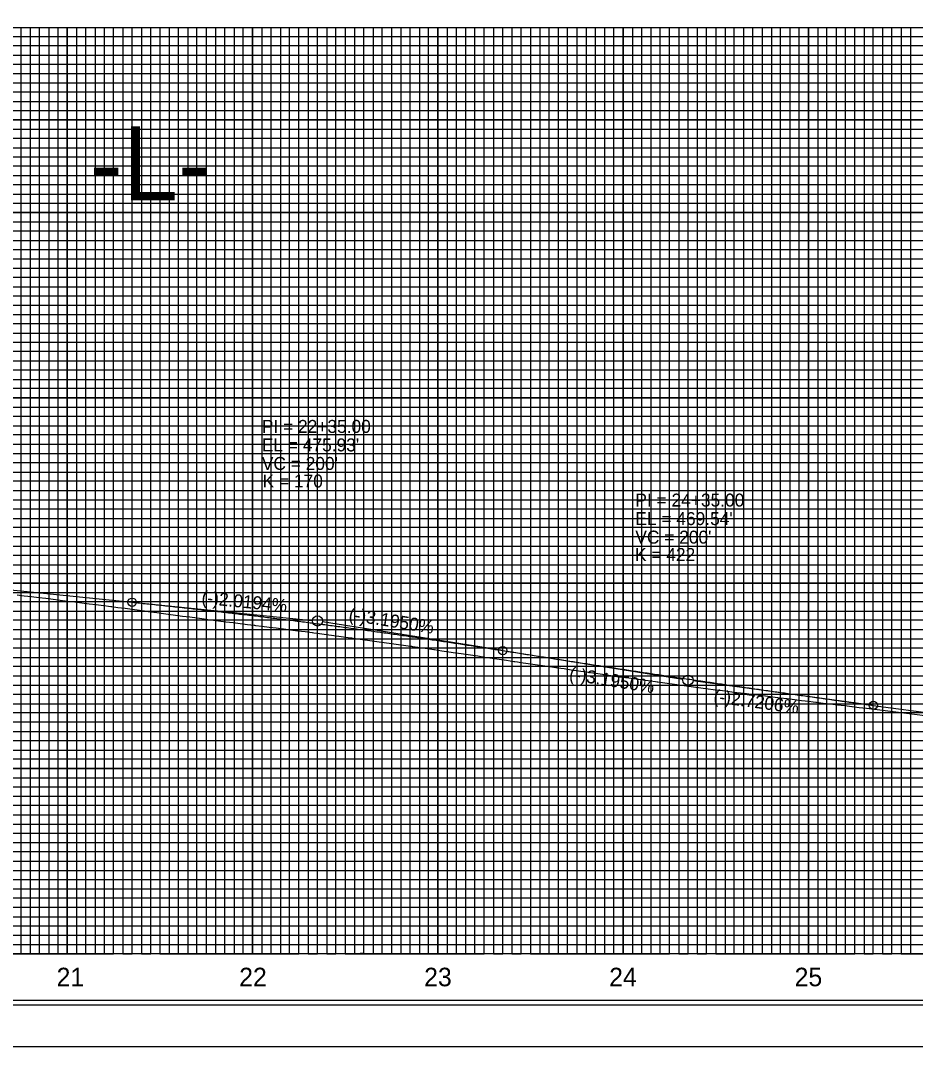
# Model space of a CAD drawing. Extents: x 571503 to 593215, y -77195 to -51828.
# Drawn here: x 583172 to 583655, y -72483 to -71929 of the extents above; entities that cross this region are included whole.
import ezdxf

# ---------------------------------------------------------------- set-up
doc = ezdxf.new("R2010")
doc.units = 0
for name, color, linetype in [('Exist Vertical Profile Ground Line', 7, 'Continuous'), ('Exist Vertical Profile Horizontal Axis Label Major', 7, 'Continuous'), ('Exist Vertical Profile Vertical Axis Label', 7, 'Continuous'), ('Prop Vertical Profile Curve Label', 7, 'Continuous'), ('Prop Vertical Profile Grade', 7, 'Continuous'), ('Prop Vertical Profile Grade Label', 7, 'Continuous'), ('Prop VPI Label', 7, 'Continuous'), ('Sheet Cutting Line CELL', 7, 'Continuous'), ('Sheet DOT Grid CELL', 7, 'Continuous'), ('Sheet Layout Profile Border Port 2', 7, 'Continuous'), ('Sheet Plot Border Inside CELL', 7, 'Continuous'), ('Sheet Plot Border Outside CELL', 7, 'Continuous'), ('Sheet Profile CELL', 7, 'Continuous'), ('Sheet Profile Grid Major CELL', 7, 'Continuous'), ('Sheet Profile Grid Middle CELL', 7, 'Continuous'), ('Sheet Profile Grid Minor CELL', 7, 'Continuous')]:
    doc.layers.add(name, color=color, linetype=linetype)

msp = doc.modelspace()

# ---------------------------------------------------------------- linework, layer by layer
at = {"layer": 'Exist Vertical Profile Ground Line'}
for points in [[(583169.91, -72239.15), (583173.79, -72239.6), (583177.67, -72240.05), (583181.56, -72240.51), (583185.37, -72240.96), (583185.44, -72240.97), (583189.33, -72241.5), (583192.11, -72241.88), (583193.21, -72242.02), (583197.1, -72242.49), (583200.98, -72242.96), (583204.86, -72243.44), (583208.75, -72243.91), (583212.63, -72244.39), (583216.52, -72244.87), (583216.93, -72244.92), (583219.15, -72245.19), (583220.4, -72245.36), (583220.97, -72245.43), (583224.29, -72245.87), (583228.17, -72246.38), (583232.05, -72246.9), (583235.94, -72247.41), (583239.82, -72247.93), (583240.62, -72248.04), (583243.71, -72248.45), (583245.27, -72248.66), (583247.59, -72248.97), (583251.48, -72249.5), (583255.36, -72250.02), (583259.24, -72250.55), (583263.13, -72251.07), (583267.01, -72251.6), (583270.9, -72252.13), (583273.87, -72252.54)], [(583273.87, -72252.54), (583274.49, -72252.62), (583274.78, -72252.65), (583276.8, -72252.91), (583278.67, -72253.14), (583282.55, -72253.62), (583286.43, -72254.1), (583290.32, -72254.58), (583294.2, -72255.06), (583297.8, -72255.5), (583298.09, -72255.54), (583298.59, -72255.6), (583301.97, -72256.03), (583305.86, -72256.51), (583309.74, -72257), (583313.62, -72257.49), (583317.51, -72257.98), (583321.39, -72258.48), (583325.28, -72258.97), (583329.16, -72259.47), (583329.27, -72259.48), (583330.09, -72259.59), (583333.05, -72259.99), (583336.93, -72260.52), (583340.81, -72261.05), (583344.7, -72261.58), (583348.58, -72262.11), (583350.55, -72262.38), (583351.33, -72262.5), (583352.47, -72262.66), (583356.35, -72263.2), (583360.24, -72263.73), (583364.12, -72264.27), (583368, -72264.81), (583371.89, -72265.35), (583374.54, -72265.72), (583375.77, -72265.9), (583379.66, -72266.45), (583382.25, -72266.82), (583382.71, -72266.88), (583383.05, -72266.93), (583383.54, -72267), (583387.43, -72267.56), (583391.31, -72268.12), (583394.84, -72268.63), (583395.19, -72268.68), (583399.08, -72269.25), (583402.96, -72269.82), (583406.47, -72270.33), (583406.52, -72270.34), (583406.85, -72270.39), (583410.73, -72270.96), (583414.62, -72271.53), (583418.5, -72272.11), (583422.38, -72272.68), (583426.27, -72273.26), (583430.15, -72273.84), (583434.04, -72274.42), (583435.97, -72274.71), (583437.92, -72275), (583438.35, -72275.07), (583438.43, -72275.08), (583438.48, -72275.08), (583439.87, -72275.28), (583441.81, -72275.56), (583445.69, -72276.12), (583449.57, -72276.69), (583453.46, -72277.25), (583457.34, -72277.81), (583460.72, -72278.3), (583460.99, -72278.34), (583461.01, -72278.34), (583461.23, -72278.37), (583461.54, -72278.42), (583465.11, -72278.94), (583469, -72279.51), (583472.88, -72280.07), (583476.76, -72280.64), (583480.65, -72281.21), (583484.53, -72281.78), (583488.42, -72282.35), (583492.3, -72282.92), (583492.71, -72282.98), (583493.5, -72283.1), (583496.19, -72283.47), (583500.07, -72283.99), (583503.95, -72284.52), (583507.84, -72285.04), (583511.72, -72285.57), (583514.43, -72285.93), (583515.28, -72286.05), (583515.61, -72286.1), (583519.49, -72286.63), (583523.38, -72287.15), (583527.26, -72287.68), (583531.14, -72288.21), (583535.03, -72288.74), (583538.91, -72289.27), (583542.8, -72289.79), (583545.58, -72290.17), (583546.68, -72290.33)], [(583546.68, -72290.33), (583547.3, -72290.42), (583550.57, -72290.82), (583554.45, -72291.29), (583558.33, -72291.76), (583562.22, -72292.24), (583566.1, -72292.71), (583567.91, -72292.93), (583569.59, -72293.16), (583569.99, -72293.21), (583573.87, -72293.68), (583577.76, -72294.16), (583581.64, -72294.63), (583585.52, -72295.11), (583589.41, -72295.58), (583593.29, -72296.05), (583597.18, -72296.53), (583599.62, -72296.82), (583601.06, -72297.02), (583601.3, -72297.05), (583604.95, -72297.5), (583608.83, -72297.97), (583612.71, -72298.45), (583616.6, -72298.92), (583620.48, -72299.39), (583620.57, -72299.4), (583620.63, -72299.42), (583621.91, -72299.56), (583624.37, -72299.86), (583628.25, -72300.33), (583652.73, -72303.32), (583652.76, -72303.32), (583674.03, -72305.96)]]:
    msp.add_lwpolyline(points, dxfattribs=at)
at = {"layer": 'Prop Vertical Profile Curve Label'}
for centre in [(583231.98, -72243.1), (583431.98, -72269.17), (583431.98, -72269.17), (583631.98, -72298.75)]:
    msp.add_circle(centre, 2.25, dxfattribs=at)
at = {"layer": 'Prop Vertical Profile Grade'}
for p, q in [((583071.98, -72226.95), (583231.98, -72243.1)), ((583631.98, -72298.75), (583896.98, -72334.8))]:
    msp.add_line(p, q, dxfattribs=at)
for points in [[(583231.98, -72243.1), (583235.98, -72243.51), (583239.98, -72243.92), (583243.98, -72244.33), (583247.98, -72244.75), (583251.98, -72245.18), (583255.98, -72245.61), (583259.98, -72246.04), (583263.98, -72246.48), (583267.98, -72246.93), (583271.98, -72247.37), (583275.98, -72247.83), (583279.98, -72248.29), (583283.98, -72248.75), (583287.98, -72249.22), (583291.98, -72249.69), (583295.98, -72250.16), (583299.98, -72250.65), (583303.98, -72251.13), (583307.98, -72251.62), (583311.98, -72252.12), (583315.98, -72252.62), (583319.98, -72253.12), (583323.98, -72253.63), (583327.98, -72254.15), (583331.98, -72254.67), (583335.98, -72255.19), (583339.98, -72255.72), (583343.98, -72256.25), (583347.98, -72256.79), (583351.98, -72257.33), (583355.98, -72257.88), (583359.98, -72258.43), (583363.98, -72258.99), (583367.98, -72259.55), (583371.98, -72260.12), (583375.98, -72260.69), (583379.98, -72261.26), (583383.98, -72261.84), (583387.98, -72262.43), (583391.98, -72263.02), (583395.98, -72263.61), (583399.98, -72264.21), (583403.98, -72264.82), (583407.98, -72265.42), (583411.98, -72266.04), (583415.98, -72266.65), (583419.98, -72267.28), (583423.98, -72267.9), (583427.98, -72268.54), (583431.98, -72269.17)], [(583431.98, -72269.17), (583435.98, -72269.81), (583439.98, -72270.45), (583443.98, -72271.08), (583447.98, -72271.71), (583451.98, -72272.34), (583455.98, -72272.97), (583459.98, -72273.6), (583463.98, -72274.22), (583467.98, -72274.85), (583471.98, -72275.47), (583475.98, -72276.09), (583479.98, -72276.7), (583483.98, -72277.32), (583487.98, -72277.93), (583491.98, -72278.54), (583495.98, -72279.15), (583499.98, -72279.76), (583503.98, -72280.37), (583507.98, -72280.97), (583511.98, -72281.57), (583515.98, -72282.17), (583519.98, -72282.77), (583523.98, -72283.37), (583527.98, -72283.96), (583531.98, -72284.55), (583535.98, -72285.15), (583539.98, -72285.73), (583543.98, -72286.32), (583547.98, -72286.91), (583551.98, -72287.49), (583555.98, -72288.07), (583559.98, -72288.65), (583563.98, -72289.23), (583567.98, -72289.8), (583571.98, -72290.38), (583575.98, -72290.95), (583579.98, -72291.52), (583583.98, -72292.08), (583587.98, -72292.65), (583591.98, -72293.21), (583595.98, -72293.78), (583599.98, -72294.34), (583603.98, -72294.9), (583607.98, -72295.45), (583611.98, -72296.01), (583615.98, -72296.56), (583619.98, -72297.11), (583623.98, -72297.66), (583627.98, -72298.21), (583631.98, -72298.75)]]:
    msp.add_spline(points, degree=3, dxfattribs=at)
at = {"layer": 'Prop VPI Label'}
for p, q in [((583231.98, -72243.1), (583329.25, -72252.92)), ((583431.98, -72269.17), (583334.7, -72253.63)), ((583431.98, -72269.17), (583529.27, -72284.71)), ((583631.98, -72298.75), (583534.71, -72285.52))]:
    msp.add_line(p, q, dxfattribs=at)
for centre in [(583331.98, -72253.2), (583531.98, -72285.15)]:
    msp.add_circle(centre, 2.75, dxfattribs=at)
at = {"layer": 'Sheet Cutting Line CELL'}
msp.add_line((582329.98, -72482.85), (584013.98, -72482.85), dxfattribs=at)
at = {"layer": 'Sheet DOT Grid CELL'}
for p, q in [((582496.98, -71932.85), (583996.87, -71932.85)), ((583196.98, -71932.85), (583196.98, -72432.85)), ((583246.98, -71932.85), (583246.98, -72432.85)), ((583296.98, -71932.85), (583296.98, -72432.85)), ((583346.98, -71932.85), (583346.98, -72432.85)), ((583396.98, -71932.85), (583396.98, -72432.85)), ((583446.98, -71932.85), (583446.98, -72432.85)), ((583496.98, -71932.85), (583496.98, -72432.85)), ((583546.98, -71932.85), (583546.98, -72432.85)), ((583596.98, -71932.85), (583596.98, -72432.85)), ((583646.98, -71932.85), (583646.98, -72432.85)), ((582496.98, -71982.85), (583996.87, -71982.85)), ((582496.98, -72032.85), (583996.87, -72032.85)), ((582496.98, -72082.85), (583996.87, -72082.85)), ((582496.98, -72132.85), (583996.87, -72132.85)), ((582496.98, -72182.85), (583996.87, -72182.85)), ((582496.98, -72232.85), (583996.87, -72232.85)), ((582496.98, -72282.85), (583996.87, -72282.85)), ((582496.98, -72332.85), (583996.87, -72332.85)), ((582496.98, -72382.85), (583996.87, -72382.85))]:
    msp.add_line(p, q, dxfattribs=at)
at = {"layer": 'Sheet Layout Profile Border Port 2'}
msp.add_lwpolyline([(582546.98, -71932.85), (583946.98, -71932.85), (583946.98, -72432.85), (582546.98, -72432.85)], close=True, dxfattribs=at)
at = {"layer": 'Sheet Plot Border Inside CELL'}
msp.add_lwpolyline([(582342.98, -72460.4), (584009.48, -72460.4), (584009.48, -71405.3), (582342.98, -71405.3)], close=True, dxfattribs=at)
at = {"layer": 'Sheet Plot Border Outside CELL'}
msp.add_lwpolyline([(582329.98, -72482.85), (584013.98, -72482.85), (584013.98, -71382.85), (582329.98, -71382.85)], close=True, dxfattribs=at)
at = {"layer": 'Sheet Profile CELL'}
for p, q in [((582496.98, -71932.85), (583996.98, -71932.85)), ((583996.98, -72432.85), (582496.98, -72432.85)), ((582496.98, -72457.85), (583996.98, -72457.85))]:
    msp.add_line(p, q, dxfattribs=at)
msp.add_lwpolyline([(583996.98, -71407.85), (582496.98, -71407.85), (582496.98, -72457.85), (583996.98, -72457.85)], close=True, dxfattribs=at)
at = {"layer": 'Sheet Profile Grid Major CELL'}
for p, q in [((583196.98, -71932.85), (583246.98, -71932.85)), ((583296.98, -71932.85), (583346.98, -71932.85)), ((583396.98, -71932.85), (583446.98, -71932.85)), ((583496.98, -71932.85), (583546.98, -71932.85)), ((583596.98, -71932.85), (583646.98, -71932.85))]:
    msp.add_line(p, q, dxfattribs=at)
for points in [[(583146.98, -72432.85), (583196.98, -72432.85), (583196.98, -71932.85), (583246.98, -71932.85), (583246.98, -72432.85), (583296.98, -72432.85), (583296.98, -71932.85), (583346.98, -71932.85), (583346.98, -72432.85), (583396.98, -72432.85), (583396.98, -71932.85), (583446.98, -71932.85), (583446.98, -72432.85), (583496.98, -72432.85), (583496.98, -71932.85), (583546.98, -71932.85), (583546.98, -72432.85), (583596.98, -72432.85), (583596.98, -71932.85), (583646.98, -71932.85), (583646.98, -72432.85), (583696.98, -72432.85)], [(583996.98, -71982.85), (582496.98, -71982.85)], [(583996.98, -72032.85), (582496.98, -72032.85), (582496.98, -72082.85), (583996.98, -72082.85)], [(583996.98, -72132.85), (582496.98, -72132.85), (582496.98, -72182.85), (583996.98, -72182.85)], [(583996.98, -72232.85), (582496.98, -72232.85), (582496.98, -72282.85), (583996.98, -72282.85)], [(583996.98, -72332.85), (582496.98, -72332.85), (582496.98, -72332.85), (582496.98, -72382.85), (583996.98, -72382.85)], [(583996.98, -72432.85), (582496.98, -72432.85)]]:
    msp.add_lwpolyline(points, dxfattribs=at)
at = {"layer": 'Sheet Profile Grid Middle CELL'}
for points in [[(583121.98, -71932.85), (583171.98, -71932.85), (583171.98, -72432.85), (583221.98, -72432.85), (583221.98, -71932.85), (583271.98, -71932.85), (583271.98, -72432.85), (583321.98, -72432.85), (583321.98, -71932.85), (583371.98, -71932.85), (583371.98, -72432.85), (583421.98, -72432.85), (583421.98, -71932.85), (583471.98, -71932.85), (583471.98, -72432.85), (583521.98, -72432.85), (583521.98, -71932.85), (583571.98, -71932.85), (583571.98, -72432.85), (583621.98, -72432.85), (583621.98, -71932.85), (583671.98, -71932.85)], [(582496.98, -71957.85), (583996.98, -71957.85)], [(583996.98, -72007.85), (582496.98, -72007.85), (582496.98, -72057.85), (583996.98, -72057.85)], [(583996.98, -72107.85), (582496.98, -72107.85), (582496.98, -72157.85), (583996.98, -72157.85)], [(583996.98, -72207.85), (582496.98, -72207.85), (582496.98, -72257.85), (583996.98, -72257.85)], [(583996.98, -72307.85), (582496.98, -72307.85), (582496.98, -72357.85), (583996.98, -72357.85)], [(583996.98, -72407.85), (582496.98, -72407.85)]]:
    msp.add_lwpolyline(points, dxfattribs=at)
at = {"layer": 'Sheet Profile Grid Minor CELL'}
for p, q in [((582546.98, -71937.85), (583946.98, -71937.85)), ((583946.98, -71942.85), (582546.98, -71942.85)), ((582546.98, -71947.85), (583946.98, -71947.85)), ((583946.98, -71952.85), (582546.98, -71952.85)), ((582546.98, -71962.85), (583946.98, -71962.85)), ((583946.98, -71967.85), (582546.98, -71967.85)), ((582546.98, -71972.85), (583946.98, -71972.85)), ((583946.98, -71977.85), (582546.98, -71977.85)), ((582546.98, -71987.85), (583946.98, -71987.85)), ((583946.98, -71992.85), (582546.98, -71992.85)), ((582546.98, -71997.85), (583946.98, -71997.85)), ((583946.98, -72002.85), (582546.98, -72002.85)), ((582546.98, -72012.85), (583946.98, -72012.85)), ((583946.98, -72017.85), (582546.98, -72017.85)), ((582546.98, -72022.85), (583946.98, -72022.85)), ((583946.98, -72027.85), (582546.98, -72027.85)), ((582546.98, -72037.85), (583946.98, -72037.85)), ((583946.98, -72042.85), (582546.98, -72042.85)), ((582546.98, -72047.85), (583946.98, -72047.85)), ((583946.98, -72052.85), (582546.98, -72052.85)), ((582546.98, -72062.85), (583946.98, -72062.85)), ((583946.98, -72067.85), (582546.98, -72067.85)), ((582546.98, -72072.85), (583946.98, -72072.85)), ((583946.98, -72077.85), (582546.98, -72077.85)), ((582546.98, -72087.85), (583946.98, -72087.85)), ((583946.98, -72092.85), (582546.98, -72092.85)), ((582546.98, -72097.85), (583946.98, -72097.85)), ((583946.98, -72102.85), (582546.98, -72102.85)), ((582546.98, -72112.85), (583946.98, -72112.85)), ((583946.98, -72117.85), (582546.98, -72117.85)), ((582546.98, -72122.85), (583946.98, -72122.85)), ((583946.98, -72127.85), (582546.98, -72127.7)), ((582546.98, -72137.85), (583946.98, -72137.85)), ((583946.98, -72142.85), (582546.98, -72142.85)), ((582546.98, -72147.85), (583946.98, -72147.85)), ((583946.98, -72152.85), (582546.98, -72152.85)), ((582546.98, -72162.85), (583946.98, -72162.85)), ((583946.98, -72167.85), (582546.98, -72167.85)), ((582546.98, -72172.85), (583946.98, -72172.85)), ((583946.98, -72177.85), (582546.98, -72177.85)), ((582546.98, -72187.85), (583946.98, -72187.85)), ((583946.98, -72192.85), (582546.98, -72192.85)), ((582546.98, -72197.85), (583946.98, -72197.85)), ((583946.98, -72202.85), (582546.98, -72202.85)), ((582546.98, -72212.85), (583946.98, -72212.85)), ((583946.98, -72217.85), (582546.98, -72217.85)), ((582546.98, -72222.85), (583946.98, -72222.85)), ((583946.98, -72227.85), (582546.98, -72227.85)), ((582546.98, -72237.85), (583946.98, -72237.85)), ((583946.98, -72242.85), (582546.98, -72242.85)), ((582546.98, -72247.85), (583946.98, -72247.85)), ((583946.98, -72252.85), (582546.98, -72252.85)), ((582546.98, -72262.85), (583946.98, -72262.85)), ((583946.98, -72267.85), (582546.98, -72267.85)), ((582546.98, -72272.85), (583946.98, -72272.85)), ((583946.98, -72277.85), (582546.98, -72277.85)), ((582546.98, -72287.85), (583946.98, -72287.85)), ((583946.98, -72292.85), (582546.98, -72292.85)), ((582546.98, -72297.85), (583946.98, -72297.85)), ((583946.98, -72302.85), (582546.98, -72302.85)), ((582546.98, -72312.85), (583946.98, -72312.85)), ((583946.98, -72317.85), (582546.98, -72317.85)), ((582546.98, -72322.85), (583946.98, -72322.85)), ((583946.98, -72327.85), (582546.98, -72327.85)), ((582546.98, -72337.85), (583946.98, -72337.85)), ((583946.98, -72342.85), (582546.98, -72342.85)), ((582546.98, -72347.85), (583946.98, -72347.85)), ((583946.98, -72352.85), (582546.98, -72352.85)), ((582546.98, -72362.85), (583946.98, -72362.85)), ((583946.98, -72367.85), (582546.98, -72367.85)), ((582546.98, -72372.85), (583946.98, -72372.85)), ((583946.98, -72377.85), (582546.98, -72377.85)), ((582546.98, -72387.85), (583946.98, -72387.85)), ((583946.98, -72392.85), (582546.98, -72392.85)), ((582546.98, -72397.85), (583946.98, -72397.85)), ((583946.98, -72402.85), (582546.98, -72402.85)), ((582546.98, -72412.85), (583946.98, -72412.85)), ((583946.98, -72417.85), (582546.98, -72417.85)), ((582546.98, -72422.85), (583946.98, -72422.85)), ((582546.98, -72427.85), (583946.98, -72427.85))]:
    msp.add_line(p, q, dxfattribs=at)
for points in [[(583166.98, -71932.85), (583176.98, -71932.85), (583176.98, -72432.85), (583181.98, -72432.85), (583181.98, -71932.85), (583186.98, -71932.85), (583186.98, -72432.85), (583191.98, -72432.85), (583191.98, -71932.85), (583201.98, -71932.85), (583201.98, -72432.85), (583201.98, -72432.85), (583206.98, -72432.85), (583206.98, -71932.85), (583211.98, -71932.85), (583211.98, -72432.85), (583216.98, -72432.85), (583216.98, -71932.85), (583226.98, -71932.85), (583226.98, -72432.85), (583231.98, -72432.85), (583231.98, -71932.85), (583236.98, -71932.85), (583236.98, -72432.85), (583241.98, -72432.85), (583241.98, -71932.85), (583251.98, -71932.85), (583251.98, -72432.85), (583256.98, -72432.85), (583256.98, -71932.85), (583261.98, -71932.85), (583261.98, -72432.85), (583266.98, -72432.85), (583266.98, -71932.85), (583276.98, -71932.85), (583276.98, -72432.85), (583281.98, -72432.85), (583281.98, -71932.85), (583286.98, -71932.85), (583286.98, -72432.85), (583291.98, -72432.85), (583291.98, -71932.85), (583301.98, -71932.85), (583301.98, -72432.85), (583306.98, -72432.85), (583306.98, -71932.85), (583311.98, -71932.85), (583311.98, -72432.85), (583316.98, -72432.85), (583316.98, -71932.85), (583326.98, -71932.85), (583326.98, -72432.85), (583331.98, -72432.85), (583331.98, -71932.85), (583336.98, -71932.85), (583336.98, -72432.85), (583341.98, -72432.85), (583341.98, -71932.85), (583351.98, -71932.85), (583351.98, -72432.85), (583356.68, -72432.3), (583356.98, -72432.85), (583356.98, -71932.85), (583361.98, -71932.85), (583361.98, -72432.85), (583366.98, -72432.85), (583366.98, -71932.85), (583376.98, -71932.85), (583376.98, -72432.85), (583381.98, -72432.85)], [(583381.98, -72432.85), (583381.98, -71932.85), (583386.98, -71932.85), (583386.98, -72432.85), (583391.98, -72432.85), (583391.98, -71932.85), (583401.98, -71932.85), (583401.98, -72432.85), (583406.98, -72432.85), (583406.98, -71932.85), (583411.98, -71932.85), (583411.98, -72432.85), (583416.98, -72432.85), (583416.98, -71932.85), (583426.98, -71932.85), (583426.98, -72432.85), (583431.98, -72432.85), (583431.98, -71932.85), (583436.98, -71932.85), (583436.98, -72432.85), (583441.98, -72432.85), (583441.98, -71932.85), (583451.98, -71932.85), (583451.98, -72432.85), (583456.98, -72432.85), (583456.98, -71932.85), (583461.98, -71932.85), (583461.98, -72432.85), (583466.98, -72432.85), (583466.98, -71932.85), (583476.98, -71932.85), (583476.98, -72432.85), (583481.98, -72432.85), (583481.98, -71932.85), (583486.98, -71932.85), (583486.98, -72432.85), (583491.98, -72432.85), (583491.98, -71932.85), (583501.98, -71932.85), (583501.98, -72432.85), (583506.98, -72432.85), (583506.98, -71932.85), (583511.98, -71932.85), (583511.98, -72432.85), (583516.98, -72432.85), (583516.98, -71932.85), (583526.98, -71932.85), (583526.98, -72432.85), (583531.98, -72432.85), (583531.98, -71932.85), (583536.98, -71932.85), (583536.98, -72432.85), (583541.98, -72432.85), (583541.98, -71932.85), (583551.98, -71932.85), (583551.98, -72432.85), (583556.98, -72432.85), (583556.98, -71932.85), (583561.98, -71932.85), (583561.98, -72432.85), (583566.98, -72432.85), (583566.98, -71932.85), (583576.98, -71932.85), (583576.98, -72432.85), (583581.98, -72432.85), (583581.98, -71932.85), (583586.98, -71932.85), (583586.98, -72432.85), (583591.98, -72432.85), (583591.98, -71932.85), (583601.98, -71932.85), (583601.98, -72432.85), (583606.98, -72432.85), (583606.98, -71932.85), (583611.98, -71932.85), (583611.98, -72432.85), (583616.98, -72432.85), (583616.98, -71932.85), (583626.98, -71932.85), (583626.98, -72432.85), (583631.98, -72432.85), (583631.98, -71932.85), (583636.98, -71932.85), (583636.98, -72432.85), (583641.98, -72432.85), (583641.98, -71932.85), (583651.98, -71932.85), (583651.98, -72432.85), (583656.98, -72432.85)]]:
    msp.add_lwpolyline(points, dxfattribs=at)

# ---------------------------------------------------------------- texts
at = {"layer": 'Exist Vertical Profile Horizontal Axis Label Major'}
for s, p in [('21', (583191.21, -72450.35)), ('22', (583289.76, -72450.35)), ('23', (583389.59, -72450.35)), ('24', (583489.44, -72450.35)), ('25', (583589.53, -72450.35))]:
    msp.add_text(s, height=10, dxfattribs=at).set_placement(p)
at = {"layer": 'Exist Vertical Profile Vertical Axis Label'}
msp.add_text('-L-', height=40, dxfattribs=at).set_placement((583209.08, -72026.21))
at = {"layer": 'Prop Vertical Profile Curve Label'}
for s, p in [("VC = 200'", (583301.97, -72171.7)), ('K = 170', (583302.39, -72181.18)), ("VC = 200'", (583503.56, -72211.47)), ('K = 422', (583503.35, -72220.86))]:
    msp.add_text(s, height=7, dxfattribs=at).set_placement(p)
at = {"layer": 'Prop Vertical Profile Grade Label'}
for s, rotation, p in [('(-)2.0194%', 354.2343, (583269.19, -72243.84)), ('(-)3.1950%', 350.9237, (583348.56, -72252.81)), ('(-)3.1950%', 350.9237, (583467.51, -72284.97)), ('(-)2.7206%', 352.2536, (583545.48, -72297.08))]:
    msp.add_text(s, height=7, rotation=rotation, dxfattribs=at).set_placement(p)
at = {"layer": 'Prop VPI Label'}
for s, p in [('PI = 22+35.00', (583301.97, -72151.7)), ("EL = 475.93'", (583301.97, -72161.7)), ('PI = 24+35.00', (583503.56, -72191.47)), ("EL = 469.54'", (583503.56, -72201.47))]:
    msp.add_text(s, height=7, dxfattribs=at).set_placement(p)

doc.saveas('drawing.dxf')
